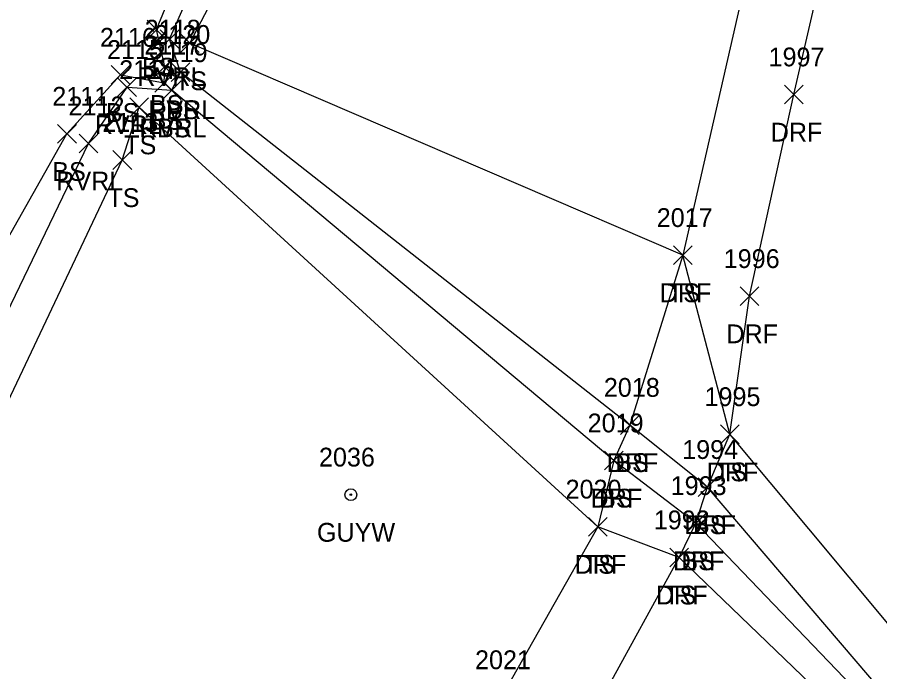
# Model space of a CAD drawing. Extents: x 1600395 to 1603269, y 874955 to 877143.
# Drawn here: x 1601910.3 to 1602002, y 875337.1 to 875406.7 of the extents above; entities that cross this region are included whole.
import ezdxf

# ---------------------------------------------------------------- set-up
doc = ezdxf.new("R2010")
doc.units = 0
for name, color, linetype in [('L_A', 7, 'Continuous'), ('L_I', 7, 'Continuous'), ('L_TIC', 7, 'Continuous'), ('LAWE', 7, 'Continuous'), ('LELB', 7, 'Continuous'), ('R_A', 7, 'Continuous'), ('R_I', 7, 'Continuous'), ('R_TIC', 7, 'Continuous'), ('RDF', 7, 'Continuous'), ('U_A', 7, 'Continuous'), ('U_I', 7, 'Continuous'), ('UPGW', 7, 'Continuous')]:
    doc.layers.add(name, color=color, linetype=linetype)

msp = doc.modelspace()

# ---------------------------------------------------------------- linework, layer by layer
at = {"layer": 'L_TIC'}
for points in [[(1601924.102, 875404.413), (1601926.102, 875406.413)], [(1601926.102, 875404.413), (1601924.102, 875406.413)], [(1601925.508, 875403.409), (1601927.508, 875405.409)], [(1601927.508, 875403.409), (1601925.508, 875405.409)], [(1601927.659, 875402.973), (1601929.659, 875404.973)], [(1601929.659, 875402.973), (1601927.659, 875404.973)], [(1601927.659, 875402.973), (1601929.659, 875404.973)], [(1601929.659, 875402.973), (1601927.659, 875404.973)], [(1601924.98, 875400.458), (1601926.98, 875402.458)], [(1601926.98, 875400.458), (1601924.98, 875402.458)], [(1601920.272, 875399.595), (1601922.272, 875401.595)], [(1601922.272, 875399.595), (1601920.272, 875401.595)], [(1601926.656, 875399.898), (1601928.656, 875401.898)], [(1601928.656, 875399.898), (1601926.656, 875401.898)], [(1601926.656, 875399.898), (1601928.656, 875401.898)], [(1601928.656, 875399.898), (1601926.656, 875401.898)], [(1601920.976, 875398.296), (1601922.976, 875400.296)], [(1601922.976, 875398.296), (1601920.976, 875400.296)], [(1601924.937, 875398.764), (1601926.937, 875400.764)], [(1601926.937, 875398.764), (1601924.937, 875400.764)], [(1601925.726, 875397.957), (1601927.726, 875399.957)], [(1601927.726, 875397.957), (1601925.726, 875399.957)], [(1601925.726, 875397.957), (1601927.726, 875399.957)], [(1601927.726, 875397.957), (1601925.726, 875399.957)], [(1601922.263, 875396.154), (1601924.263, 875398.154)], [(1601924.263, 875396.154), (1601922.263, 875398.154)], [(1601922.263, 875396.154), (1601924.263, 875398.154)], [(1601924.263, 875396.154), (1601922.263, 875398.154)], [(1601914.581, 875393.322), (1601916.581, 875395.322)], [(1601916.581, 875393.322), (1601914.581, 875395.322)], [(1601916.879, 875392.303), (1601918.879, 875394.303)], [(1601918.879, 875392.303), (1601916.879, 875394.303)], [(1601920.47, 875390.541), (1601922.47, 875392.541)], [(1601922.47, 875390.541), (1601920.47, 875392.541)], [(1601980.095, 875380.42), (1601982.095, 875382.42)], [(1601982.095, 875380.42), (1601980.095, 875382.42)], [(1601974.467, 875362.358), (1601976.467, 875364.358)], [(1601976.467, 875362.358), (1601974.467, 875364.358)], [(1601985.103, 875361.37), (1601987.103, 875363.37)], [(1601987.103, 875361.37), (1601985.103, 875363.37)], [(1601972.752, 875358.576), (1601974.752, 875360.576)], [(1601974.752, 875358.576), (1601972.752, 875360.576)], [(1601982.723, 875355.75), (1601984.723, 875357.75)], [(1601984.723, 875355.75), (1601982.723, 875357.75)], [(1601971.052, 875351.536), (1601973.052, 875353.536)], [(1601973.052, 875351.536), (1601971.052, 875353.536)], [(1601981.496, 875351.908), (1601983.496, 875353.908)], [(1601983.496, 875351.908), (1601981.496, 875353.908)], [(1601979.703, 875348.267), (1601981.703, 875350.267)], [(1601981.703, 875348.267), (1601979.703, 875350.267)]]:
    msp.add_lwpolyline(points, dxfattribs=at)
at = {"layer": 'LAWE'}
msp.add_lwpolyline([(1601739.843, 875093.177), (1601757.337, 875121.493), (1601768.463, 875137.841), (1601782.196, 875157.26), (1601805.115, 875181.224), (1601811.363, 875189.98), (1601818.624, 875191.892), (1601823.213, 875192.812), (1601844.145, 875211.079), (1601861.587, 875229.673), (1601864.028, 875235.309), (1601870.344, 875255.068), (1601872.905, 875271.961), (1601871.033, 875274.538), (1601876.566, 875297.895), (1601887.708, 875330.048), (1601901.388, 875359.117), (1601917.879, 875393.303), (1601921.976, 875399.296), (1601926.726, 875398.957), (1601927.656, 875400.898), (1601926.508, 875404.409), (1601936.606, 875427.424)], dxfattribs=at)
at = {"layer": 'LELB'}
for points in [[(1601870.716, 875282.068), (1601873.73, 875299.558), (1601885.112, 875329.711), (1601896.518, 875360.64), (1601915.581, 875394.322), (1601921.272, 875400.595), (1601925.937, 875399.764), (1601925.98, 875401.458), (1601925.102, 875405.413), (1601934.858, 875429.076), (1601950.13, 875458.965), (1601969.101, 875502.618), (1601979.94, 875529.952), (1601991.868, 875574.723)], [(1601928.659, 875403.973), (1601940.671, 875426.978), (1601955.288, 875459.024), (1601970.267, 875502.332)], [(1602130.783, 875324.366), (1602086.452, 875323.551), (1602047.678, 875325.814), (1602011.495, 875331.951), (1601986.103, 875362.37), (1601981.095, 875381.42), (1601928.659, 875403.973)], [(1602130.81, 875321.995), (1602086.811, 875321.908), (1602044.285, 875322.579), (1602008.888, 875327.294), (1601983.723, 875356.75), (1601975.467, 875363.358), (1601927.656, 875400.898)], [(1602174.044, 875317.39), (1602130.358, 875320.318), (1602087.226, 875319.39), (1602042.601, 875319.821), (1602008.236, 875326.09), (1601982.496, 875352.908), (1601973.752, 875359.576), (1601926.726, 875398.957)], [(1601878.451, 875296.907), (1601888.82, 875327.576), (1601904.604, 875356.016), (1601921.47, 875391.541), (1601923.263, 875397.154)], [(1602129.738, 875318.211), (1602087.657, 875317.408), (1602041.946, 875317.605), (1602007.813, 875323.215), (1601980.703, 875349.267), (1601972.052, 875352.536), (1601923.263, 875397.154)]]:
    msp.add_lwpolyline(points, dxfattribs=at)
at = {"layer": 'R_TIC'}
for points in [[(1601991.914, 875397.509), (1601993.914, 875399.509)], [(1601993.914, 875397.509), (1601991.914, 875399.509)], [(1601980.095, 875380.42), (1601982.095, 875382.42)], [(1601982.095, 875380.42), (1601980.095, 875382.42)], [(1601987.197, 875376.056), (1601989.197, 875378.056)], [(1601989.197, 875376.056), (1601987.197, 875378.056)], [(1601974.467, 875362.358), (1601976.467, 875364.358)], [(1601976.467, 875362.358), (1601974.467, 875364.358)], [(1601985.103, 875361.37), (1601987.103, 875363.37)], [(1601987.103, 875361.37), (1601985.103, 875363.37)], [(1601972.752, 875358.576), (1601974.752, 875360.576)], [(1601974.752, 875358.576), (1601972.752, 875360.576)], [(1601982.723, 875355.75), (1601984.723, 875357.75)], [(1601984.723, 875355.75), (1601982.723, 875357.75)], [(1601971.052, 875351.536), (1601973.052, 875353.536)], [(1601973.052, 875351.536), (1601971.052, 875353.536)], [(1601981.496, 875351.908), (1601983.496, 875353.908)], [(1601983.496, 875351.908), (1601981.496, 875353.908)], [(1601979.703, 875348.267), (1601981.703, 875350.267)], [(1601981.703, 875348.267), (1601979.703, 875350.267)]]:
    msp.add_lwpolyline(points, dxfattribs=at)
at = {"layer": 'RDF'}
for points in [[(1602061.844, 875684.018), (1602044.241, 875629.479), (1602032.842, 875584.978), (1602023.304, 875548.954), (1602011.203, 875500.699), (1601997.923, 875449.957), (1601988.661, 875414.529), (1601981.095, 875381.42), (1601975.467, 875363.358), (1601973.752, 875359.576), (1601972.052, 875352.536), (1601961.766, 875334.387), (1601952.581, 875318.571), (1601943.825, 875302.36), (1601937.979, 875289.879), (1601931.35, 875281.769)], [(1601949.481, 875279.458), (1601947.406, 875284.404), (1601949.281, 875291.024), (1601956.309, 875304.783), (1601960.932, 875313.404), (1601971.122, 875331.838), (1601980.703, 875349.267), (1601982.496, 875352.908), (1601983.723, 875356.75), (1601986.103, 875362.37), (1601988.197, 875377.056), (1601992.914, 875398.509), (1602001.449, 875435.574), (1602010.573, 875469.717), (1602020.944, 875507.945), (1602032.385, 875553.275), (1602043.325, 875596.715), (1602063.594, 875669.347)]]:
    msp.add_lwpolyline(points, dxfattribs=at)
at = {"layer": 'UPGW'}
for radius in [0.625, 0.0833]:
    msp.add_circle((1601945.785, 875355.943), radius, dxfattribs=at)

# ---------------------------------------------------------------- texts
at = {"layer": 'L_A'}
for s, p in [('BS', (1601923.543, 875400.413)), ('RVRL', (1601923.075, 875399.409)), ('TS', (1601927.068, 875398.973)), ('TS', (1601927.068, 875398.973)), ('BS', (1601924.421, 875396.458)), ('BS', (1601919.713, 875395.595)), ('RVRL', (1601924.223, 875395.898)), ('BS', (1601926.097, 875395.898)), ('BS', (1601924.378, 875394.764)), ('RVRL', (1601918.543, 875394.296)), ('RVRL', (1601923.293, 875393.957)), ('BS', (1601925.167, 875393.957)), ('TS', (1601921.673, 875392.154)), ('TS', (1601921.673, 875392.154)), ('BS', (1601914.022, 875389.322)), ('RVRL', (1601914.446, 875388.303)), ('TS', (1601919.88, 875386.541)), ('TS', (1601979.505, 875376.42)), ('BS', (1601973.908, 875358.358)), ('TS', (1601984.512, 875357.37)), ('BS', (1601972.193, 875354.576)), ('BS', (1601982.164, 875351.75)), ('BS', (1601980.937, 875347.908)), ('TS', (1601970.461, 875347.536)), ('TS', (1601979.113, 875344.267))]:
    msp.add_text(s, height=2, dxfattribs=at).set_placement(p)
at = {"layer": 'L_I'}
for s, p in [('2118', (1601923.854, 875404.458)), ('2120', (1601924.877, 875403.898)), ('2120', (1601924.877, 875403.898)), ('2116', (1601919.091, 875403.595)), ('2115', (1601919.85, 875402.296)), ('2117', (1601923.811, 875402.764)), ('2119', (1601924.592, 875401.957)), ('2119', (1601924.592, 875401.957)), ('2114', (1601921.138, 875400.154)), ('2114', (1601921.138, 875400.154)), ('2111', (1601914.023, 875397.322)), ('2112', (1601915.753, 875396.303)), ('2113', (1601919.345, 875394.541)), ('2017', (1601978.324, 875384.42)), ('2018', (1601972.696, 875366.358)), ('1995', (1601983.41, 875365.37)), ('2019', (1601970.973, 875362.576)), ('1994', (1601981.031, 875359.75)), ('2020', (1601968.626, 875355.536)), ('1993', (1601979.803, 875355.908)), ('1992', (1601978.011, 875352.267))]:
    msp.add_text(s, height=2, dxfattribs=at).set_placement(p)
at = {"layer": 'R_A'}
for p in [(1601990.45, 875393.509), (1601978.631, 875376.42), (1601985.733, 875372.056), (1601973.003, 875358.358), (1601983.638, 875357.37), (1601971.287, 875354.576), (1601981.259, 875351.75), (1601980.031, 875347.908), (1601969.587, 875347.536), (1601978.239, 875344.267)]:
    msp.add_text('DRF', height=2, dxfattribs=at).set_placement(p)
at = {"layer": 'R_I'}
for s, p in [('1997', (1601990.222, 875401.509)), ('2017', (1601978.324, 875384.42)), ('1996', (1601985.45, 875380.056)), ('2018', (1601972.696, 875366.358)), ('1995', (1601983.41, 875365.37)), ('2019', (1601970.973, 875362.576)), ('1994', (1601981.031, 875359.75)), ('2020', (1601968.626, 875355.536)), ('1993', (1601979.803, 875355.908)), ('1992', (1601978.011, 875352.267)), ('2021', (1601958.995, 875337.387))]:
    msp.add_text(s, height=2, dxfattribs=at).set_placement(p)
at = {"layer": 'U_A'}
msp.add_text('GUYW', height=2, dxfattribs=at).set_placement((1601942.178, 875350.943))
at = {"layer": 'U_I'}
msp.add_text('2036', height=2, dxfattribs=at).set_placement((1601942.391, 875358.943))

doc.saveas('drawing.dxf')
